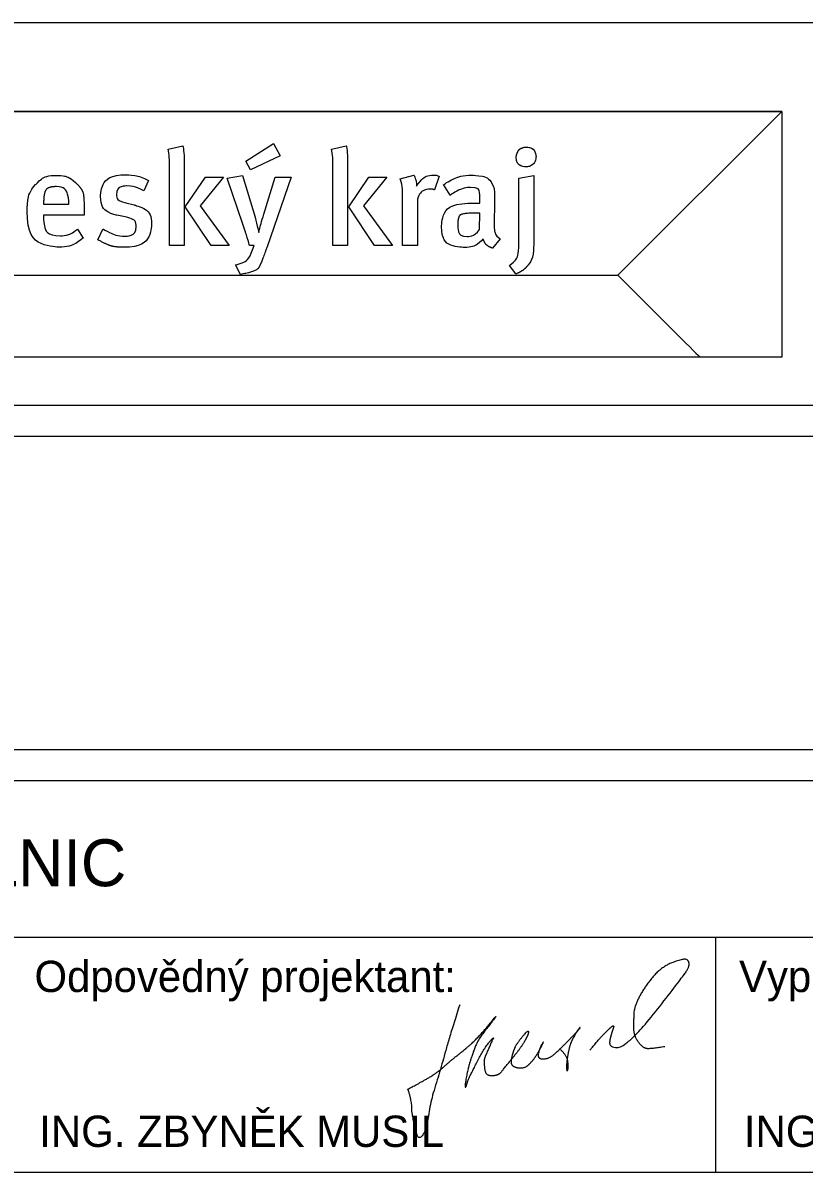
# Model space of a CAD drawing. Extents: x 1619 to 1829, y 760 to 1057.
# Drawn here: x 1679.4 to 1729.3, y 834.4 to 907.9 of the extents above; entities that cross this region are included whole.
import ezdxf

# ---------------------------------------------------------------- set-up
doc = ezdxf.new("R2010")
doc.units = 0
doc.layers.add('106_PRIKOP', color=7, linetype='Continuous')
doc.layers.add('120_ZPEVNENI', color=7, linetype='Continuous')

msp = doc.modelspace()

# ---------------------------------------------------------------- linework, layer by layer
at = {"layer": '106_PRIKOP'}
for points in [[(1715.627, 842.232), (1716.164, 842.892), (1716.764, 843.519), (1717.211, 843.909), (1717.001, 843.309), (1716.881, 842.862), (1716.881, 842.532), (1717.211, 842.382), (1717.721, 842.442), (1719.005, 843.639), (1721.489, 846.843), (1721.999, 847.59), (1721.909, 848.01), (1721.519, 848.07), (1720.202, 847.56), (1719.155, 846.333), (1718.438, 845.016), (1718.408, 843.999), (1718.408, 843.189), (1718.978, 842.382), (1719.515, 842.322), (1720.412, 842.472)], [(1707.308, 845.136), (1706.681, 843.189), (1706.081, 841.005), (1705.424, 838.878), (1705.214, 837.381), (1704.944, 836.754), (1704.707, 836.604), (1704.587, 836.754), (1704.467, 837.231), (1704.227, 838.371), (1704.257, 838.818), (1704.017, 839.748), (1703.957, 839.718), (1704.737, 840.135), (1705.844, 840.765), (1706.771, 841.602), (1707.998, 842.562), (1708.715, 843.309), (1709.612, 844.389), (1709.612, 844.359), (1708.445, 842.862), (1708.058, 841.812), (1707.818, 840.975), (1707.608, 839.868), (1707.728, 839.868), (1707.788, 840.225), (1708.145, 840.945), (1708.745, 842.112), (1709.282, 842.892), (1709.522, 843.039), (1709.402, 842.922), (1709.075, 842.142), (1708.865, 841.692), (1708.865, 841.245), (1708.955, 840.705), (1709.312, 840.585), (1709.822, 840.675), (1710.122, 841.035), (1711.229, 842.412), (1711.616, 843.069), (1711.706, 843.309), (1711.736, 843.429), (1711.586, 843.429), (1711.169, 842.922), (1710.779, 842.382), (1710.509, 841.335), (1710.929, 841.095), (1711.466, 841.095), (1711.826, 841.395), (1712.246, 841.932), (1712.753, 842.922), (1712.426, 842.412), (1712.246, 841.692), (1712.933, 841.662), (1713.503, 842.082), (1715.027, 843.639), (1714.967, 843.699), (1714.757, 843.369), (1714.4, 842.742), (1714.25, 842.172), (1714.13, 841.452), (1714.13, 840.855), (1714.25, 841.005), (1714.19, 841.872), (1713.74, 842.262)]]:
    msp.add_open_spline(points, degree=2, dxfattribs=at)
at = {"layer": '120_ZPEVNENI'}
for p, q in [((1813.65, 907.867), (1633.65, 907.867)), ((1688.678, 899.794), (1689.627, 900.027)), ((1699.113, 899.794), (1700.062, 900.027)), ((1703.507, 897.913), (1704.379, 898.136)), ((1705.992, 898.077), (1705.699, 897.196)), ((1687.433, 897.792), (1687.123, 897.135)), ((1706.695, 896.859), (1706.271, 897.542)), ((1680.732, 896.281), (1682.345, 896.281)), ((1685.974, 896.377), (1686.52, 896.237)), ((1709.525, 896.341), (1709.507, 895.09)), ((1685.94, 895.47), (1685.413, 895.582)), ((1708.569, 894.676), (1708.586, 895.712)), ((1682.89, 894.702), (1683.261, 894.124)), ((1684.189, 894.02), (1684.524, 894.702)), ((1694.475, 894.477), (1694.475, 894.486)), ((1694.173, 893.658), (1693.871, 893.658)), ((1709.888, 894.08), (1709.395, 893.476)), ((1693.302, 891.794), (1692.99, 892.406)), ((1710.895, 891.828), (1710.488, 892.38)), ((1633.65, 883.446), (1813.65, 883.446)), ((1633.65, 849.446), (1813.65, 849.446)), ((1723.65, 849.446), (1723.65, 834.446))]:
    msp.add_line(p, q, dxfattribs=at)
for points in [[(1717.41, 891.748), (1727.871, 902.209), (1638.95, 902.209), (1638.95, 891.748), (1717.41, 891.748)], [(1695.837, 899.371), (1693.939, 898.491), (1693.645, 899.034), (1695.405, 900.174), (1695.837, 899.371)], [(1689.713, 898.87), (1689.713, 893.658), (1688.773, 893.658), (1688.773, 898.741)], [(1700.148, 898.87), (1700.148, 893.658), (1699.208, 893.658), (1699.208, 898.741)], [(1691.431, 893.658), (1689.783, 896.126), (1691.076, 898.024), (1692.225, 898.024), (1690.732, 896.178), (1692.579, 893.658), (1691.431, 893.658)], [(1693.455, 895.013), (1692.464, 897.955), (1693.43, 898.12), (1694.234, 895.461)], [(1694.802, 895.66), (1695.525, 898.024), (1696.546, 898.024), (1695.001, 893.563)], [(1701.866, 893.658), (1700.219, 896.126), (1701.512, 898.024), (1702.661, 898.024), (1701.167, 896.178), (1703.015, 893.658), (1701.866, 893.658)], [(1711.075, 893.752), (1711.075, 897.955), (1712.034, 898.129), (1712.034, 893.761)], [(1704.612, 896.609), (1704.612, 893.658), (1703.661, 893.658), (1703.661, 896.738)], [(1708.31, 896.359), (1708.602, 896.359), (1708.602, 896.592)], [(1683.329, 895.781), (1683.329, 895.582), (1680.724, 895.582), (1680.724, 895.513)]]:
    msp.add_lwpolyline(points, dxfattribs=at)
for points in [[(1638.95, 902.209), (1727.871, 902.209), (1727.871, 886.517), (1638.95, 886.517)], [(1633.65, 861.446), (1813.65, 861.446), (1813.65, 881.446), (1633.65, 881.446)], [(1633.65, 834.446), (1813.65, 834.446), (1813.65, 859.446), (1633.65, 859.446)]]:
    msp.add_lwpolyline(points, close=True, dxfattribs=at)
for points, degree in [([(1688.773, 898.741), (1688.773, 898.741), (1688.773, 899.163), (1688.747, 899.457), (1688.678, 899.794)], 3), ([(1689.627, 900.027), (1689.627, 900.027), (1689.678, 899.75), (1689.713, 899.328), (1689.713, 898.87)], 3), ([(1699.208, 898.741), (1699.208, 898.741), (1699.208, 899.163), (1699.183, 899.457), (1699.113, 899.794)], 3), ([(1700.062, 900.027), (1700.062, 900.027), (1700.116, 899.75), (1700.148, 899.328), (1700.148, 898.87)], 3), ([(1710.919, 899.302), (1710.919, 899.302), (1710.919, 899.388), (1710.936, 899.466), (1710.973, 899.544)], 3), ([(1710.973, 899.544), (1711.042, 899.716), (1711.188, 899.854), (1711.36, 899.906)], 2), ([(1711.36, 899.906), (1711.36, 899.906), (1711.422, 899.932), (1711.481, 899.941), (1711.552, 899.941)], 3), ([(1711.552, 899.941), (1711.552, 899.941), (1711.896, 899.941), (1712.179, 899.655), (1712.179, 899.319)], 3), ([(1711.544, 898.671), (1711.544, 898.671), (1711.196, 898.671), (1710.919, 898.948), (1710.919, 899.302)], 3), ([(1711.912, 898.792), (1711.912, 898.792), (1711.81, 898.715), (1711.681, 898.671), (1711.544, 898.671)], 3), ([(1712.179, 899.319), (1712.179, 899.319), (1712.179, 899.096), (1712.077, 898.905), (1711.912, 898.792)], 3), ([(1680.223, 897.542), (1680.223, 897.542), (1680.576, 897.947), (1681.009, 898.129), (1681.561, 898.129)], 3), ([(1681.561, 898.129), (1681.561, 898.129), (1681.992, 898.129), (1682.388, 898.016), (1682.76, 897.68)], 3), ([(1684.368, 896.782), (1684.368, 896.782), (1684.368, 897.601), (1685.026, 898.171), (1685.991, 898.171)], 3), ([(1685.991, 898.171), (1685.991, 898.171), (1686.587, 898.171), (1687.064, 897.99), (1687.433, 897.792)], 3), ([(1704.379, 898.136), (1704.379, 898.136), (1704.483, 897.939), (1704.543, 897.688), (1704.543, 897.447)], 3), ([(1704.543, 897.447), (1704.543, 897.447), (1704.888, 897.921), (1705.232, 898.146), (1705.656, 898.146)], 3), ([(1705.656, 898.146), (1705.656, 898.146), (1705.793, 898.146), (1705.88, 898.129), (1705.992, 898.077)], 3), ([(1706.271, 897.542), (1706.271, 897.542), (1706.927, 897.955), (1707.472, 898.136), (1708.127, 898.136)], 3), ([(1708.127, 898.136), (1708.127, 898.136), (1708.807, 898.136), (1709.267, 897.886), (1709.457, 897.412)], 3), ([(1679.678, 895.833), (1679.678, 895.833), (1679.678, 896.601), (1679.844, 897.11), (1680.223, 897.542)], 3), ([(1681.561, 897.412), (1681.026, 897.412), (1680.732, 896.99), (1680.732, 896.281)], 2), ([(1682.345, 896.281), (1682.345, 896.281), (1682.345, 896.99), (1682.036, 897.412), (1681.561, 897.412)], 3), ([(1682.76, 897.68), (1683.14, 897.334), (1683.329, 896.799), (1683.329, 895.781)], 2), ([(1686.052, 897.455), (1686.052, 897.455), (1685.646, 897.455), (1685.387, 897.231), (1685.387, 896.894)], 3), ([(1687.123, 897.135), (1687.123, 897.135), (1686.717, 897.352), (1686.397, 897.455), (1686.052, 897.455)], 3), ([(1703.661, 896.738), (1703.661, 896.738), (1703.661, 897.291), (1703.603, 897.645), (1703.507, 897.913)], 3), ([(1705.431, 897.256), (1705.431, 897.256), (1705.036, 897.256), (1704.699, 896.963), (1704.612, 896.609)], 3), ([(1705.699, 897.196), (1705.604, 897.231), (1705.533, 897.256), (1705.431, 897.256)], 2), ([(1707.998, 897.36), (1707.998, 897.36), (1707.369, 897.36), (1706.695, 896.859), (1706.695, 896.859)], 3), ([(1708.602, 896.592), (1708.602, 896.592), (1708.602, 897.093), (1708.515, 897.36), (1707.998, 897.36)], 3), ([(1709.457, 897.412), (1709.457, 897.412), (1709.534, 897.222), (1709.534, 896.99), (1709.525, 896.341)], 3), ([(1685.413, 895.582), (1685.413, 895.582), (1684.758, 895.72), (1684.368, 896.169), (1684.368, 896.782)], 3), ([(1685.387, 896.894), (1685.387, 896.894), (1685.387, 896.627), (1685.535, 896.489), (1685.974, 896.377)], 3), ([(1681.689, 893.546), (1681.689, 893.546), (1680.454, 893.546), (1679.678, 894.434), (1679.678, 895.833)], 3), ([(1686.52, 896.237), (1686.52, 896.237), (1687.399, 896.014), (1687.632, 895.53), (1687.632, 895.022)], 3), ([(1706.15, 894.84), (1706.15, 894.84), (1706.15, 895.85), (1706.91, 896.359), (1708.31, 896.359)], 3), ([(1680.724, 895.513), (1680.724, 895.513), (1680.724, 894.909), (1680.947, 894.271), (1681.801, 894.271)], 3), ([(1687.632, 895.022), (1687.632, 895.022), (1687.632, 894.14), (1686.915, 893.536), (1685.862, 893.536)], 3), ([(1686.646, 894.857), (1686.646, 894.857), (1686.646, 895.194), (1686.433, 895.366), (1685.94, 895.47)], 3), ([(1693.871, 893.658), (1693.871, 893.658), (1693.749, 894.149), (1693.586, 894.624), (1693.455, 895.013)], 3), ([(1694.234, 895.461), (1694.234, 895.461), (1694.31, 895.194), (1694.475, 894.477), (1694.475, 894.477)], 3), ([(1694.475, 894.486), (1694.475, 894.486), (1694.491, 894.555), (1694.646, 895.159), (1694.802, 895.66)], 3), ([(1708.412, 895.72), (1707.464, 895.72), (1707.178, 895.444), (1707.178, 894.892)], 2), ([(1708.586, 895.712), (1708.586, 895.712), (1708.586, 895.712), (1708.482, 895.72), (1708.412, 895.72)], 3), ([(1709.507, 895.09), (1709.507, 895.09), (1709.507, 894.874), (1709.507, 894.711), (1709.534, 894.581)], 3), ([(1681.801, 894.271), (1681.801, 894.271), (1682.207, 894.271), (1682.562, 894.417), (1682.89, 894.702)], 3), ([(1684.524, 894.702), (1684.524, 894.702), (1684.912, 894.477), (1685.449, 894.244), (1685.94, 894.244)], 3), ([(1685.94, 894.244), (1685.94, 894.244), (1686.353, 894.244), (1686.646, 894.495), (1686.646, 894.857)], 3), ([(1707.601, 893.527), (1707.601, 893.527), (1706.6, 893.527), (1706.15, 894.08), (1706.15, 894.84)], 3), ([(1707.178, 894.892), (1707.178, 894.892), (1707.178, 894.477), (1707.403, 894.219), (1707.782, 894.219)], 3), ([(1707.782, 894.219), (1707.782, 894.219), (1708.082, 894.219), (1708.376, 894.4), (1708.569, 894.676)], 3), ([(1709.534, 894.581), (1709.534, 894.581), (1709.577, 894.356), (1709.681, 894.227), (1709.888, 894.08)], 3), ([(1683.261, 894.124), (1683.261, 894.124), (1682.804, 893.735), (1682.276, 893.546), (1681.689, 893.546)], 3), ([(1685.862, 893.536), (1685.327, 893.536), (1684.75, 893.709), (1684.189, 894.02)], 2), ([(1692.99, 892.406), (1692.99, 892.406), (1693.586, 892.57), (1693.921, 892.821), (1694.173, 893.658)], 3), ([(1695.001, 893.563), (1694.637, 892.511), (1694.328, 891.984), (1693.302, 891.794)], 2), ([(1708.8, 894.064), (1708.8, 894.064), (1708.447, 893.666), (1708.067, 893.527), (1707.601, 893.527)], 3), ([(1709.395, 893.476), (1709.129, 893.581), (1708.905, 893.788), (1708.8, 894.064)], 2), ([(1710.488, 892.38), (1710.488, 892.38), (1710.948, 892.699), (1711.075, 893.044), (1711.075, 893.752)], 3), ([(1712.034, 893.761), (1712.034, 893.761), (1712.034, 892.993), (1711.87, 892.648), (1711.714, 892.449)], 3), ([(1711.714, 892.449), (1711.515, 892.199), (1711.249, 891.984), (1710.895, 891.828)], 2), ([(1722.641, 886.517), (1722.641, 886.517), (1717.41, 891.748), (1717.41, 891.748), (1717.41, 891.748), (1717.41, 891.748), (1638.95, 891.748), (1638.95, 891.748), (1638.95, 891.748), (1638.95, 891.748), (1638.95, 886.517), (1638.95, 886.517), (1638.95, 886.517), (1638.95, 886.517), (1722.641, 886.517), (1722.641, 886.517)], 3)]:
    msp.add_open_spline(points, degree=degree, dxfattribs=at)

# ---------------------------------------------------------------- texts
for s, height, p in [('SILNIC A DÁLNIC', 3, (1653.462, 852.705)), ('Odpovědný projektant:', 2, (1680.15, 845.946)), ('Vypracoval:', 2, (1725.15, 845.946))]:
    msp.add_text(s, height=height, dxfattribs=at).set_placement(p)
for p in [(1680.457, 836.05), (1725.457, 836.05)]:
    msp.add_text('ING. ZBYNĚK MUSIL', height=2, rotation=360, dxfattribs=at).set_placement(p)

doc.saveas('drawing.dxf')
